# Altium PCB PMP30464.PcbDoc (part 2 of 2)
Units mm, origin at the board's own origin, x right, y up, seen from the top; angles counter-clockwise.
Board outline 89.03 x 50.29 mm, 4 copper layers (Top Layer, GND, Signal Layer, Bottom Layer), stack 2.028 mm thick; 80 components, 45 nets, 213 pads, 174 vias.
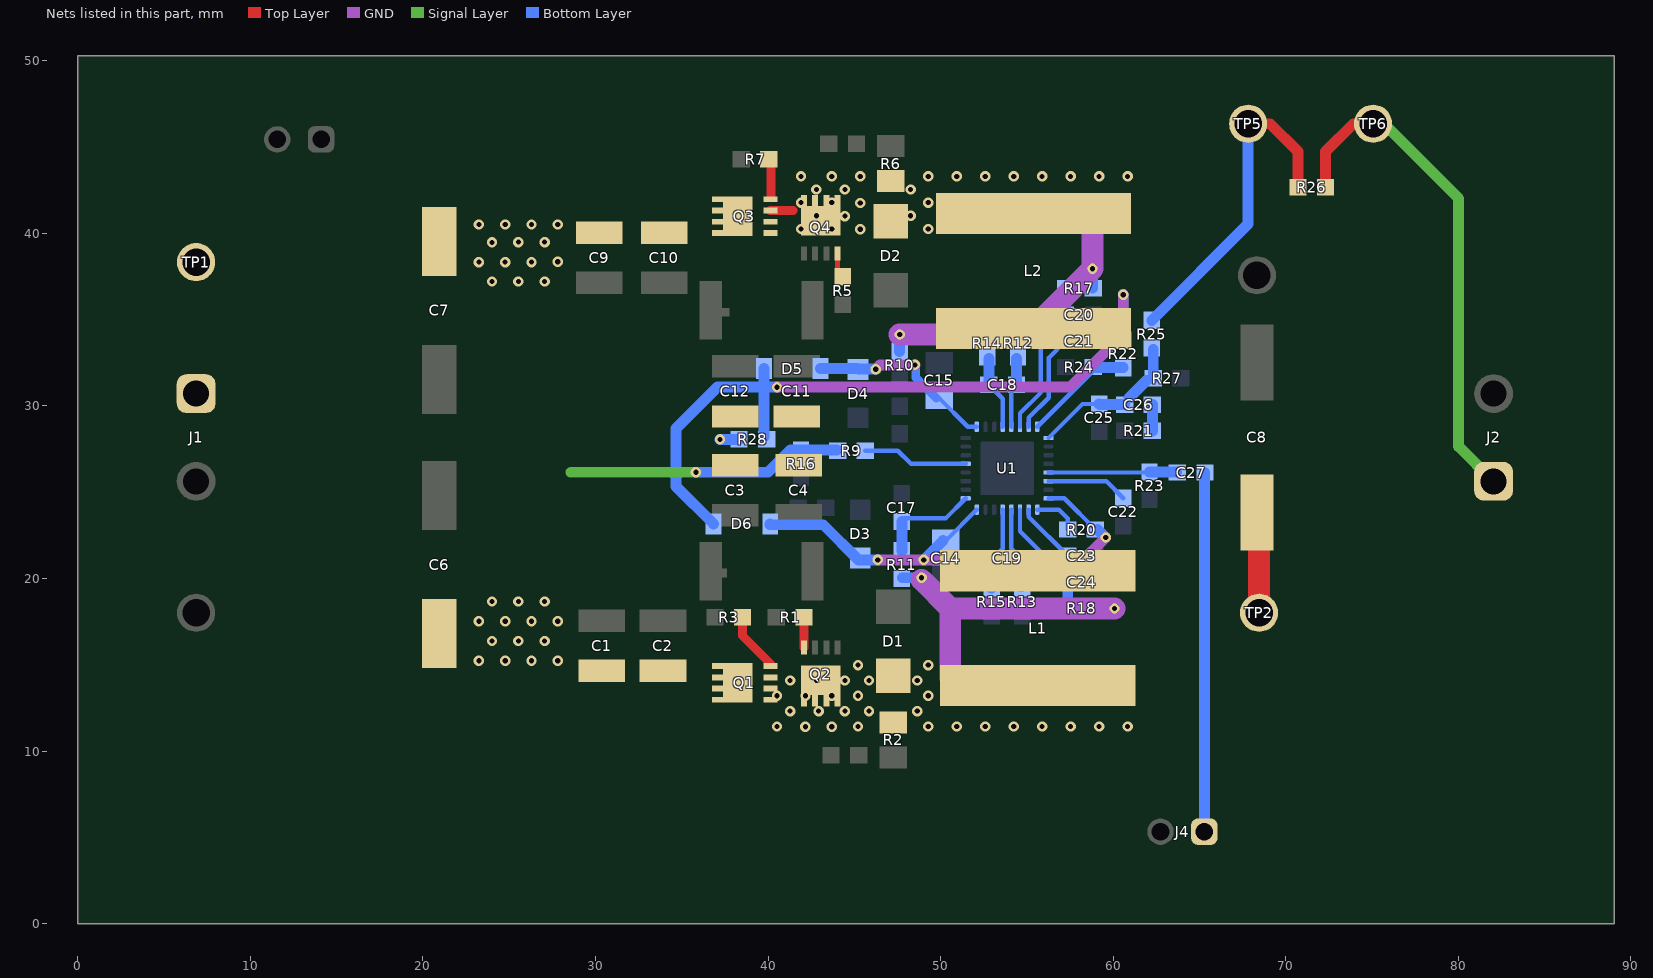
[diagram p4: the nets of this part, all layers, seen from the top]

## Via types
v1: diameter 0.6, hole 0.3, Top Layer to Bottom Layer, 170 vias
v2: diameter 5, hole 3, Top Layer to Bottom Layer, 4 vias

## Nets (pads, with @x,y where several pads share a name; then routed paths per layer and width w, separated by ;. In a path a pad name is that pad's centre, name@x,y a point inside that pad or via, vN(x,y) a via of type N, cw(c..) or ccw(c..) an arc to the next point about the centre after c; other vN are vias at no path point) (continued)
NetC17_2: C17.2 R11.2 U1.25 | length 6
  Bottom Layer w0.254: C17.2@47.75,23.312 47.923,23.485 50.283,23.485 U1.25@51.446,24.648
  Bottom Layer w0.635: R11.2@47.75,21.61 C17.2@47.75,23.312
NetC18_1: C18.1 R12.1 U1.5 | length 3.7
  Bottom Layer w0.254: U1.5@54.096,28.798 C18.1@54.096,30.928
  Bottom Layer w0.635: C18.1@54.392,31.224 R12.1@54.392,32.748
NetC18_2: C18.2 R14.1 U1.4 | length 4.3
  Bottom Layer w0.254: C18.2@52.792,31.224 53.596,30.42 U1.4@53.596,28.798
  Bottom Layer w0.635: C18.2@52.792,31.224 R14.1@52.792,32.748
NetC19_1: C19.1 R13.1 U1.20 | length 4.7
  Bottom Layer w0.254: U1.20@54.096,23.998 54.096,21.741 C19.1@54.646,21.191
  Bottom Layer w0.635: R13.1@54.646,19.54 C19.1@54.646,21.191
NetC19_2: C19.2 R15.1 U1.21 | length 4.8
  Bottom Layer w0.254: C19.2@53.046,21.191 53.596,21.741 U1.21@53.596,23.998
  Bottom Layer w0.635: R15.1@52.957,19.451 52.957,21.102 C19.2@53.046,21.191
NetC20_1: C20.1 R17.2 U1.6 | length 9.4
  Bottom Layer w0.254: U1.6@54.596,28.798 54.596,29.577 55.807,30.788 55.807,33.303 56.261,33.757 56.261,34.798 56.751,35.288 C20.1@57.237,35.288
  Bottom Layer w0.635: C20.1@57.237,35.288 R17.2@57.237,36.812
NetC21_1: C21.1 U1.7 | length 5.9
  Bottom Layer w0.254: U1.7@55.096,28.798 55.096,29.315 56.261,30.48 56.261,32.788 C21.1@57.237,33.764
NetC22_2: C22.2 U1.14 | length 4.7
  Bottom Layer w0.254: U1.14@56.246,25.648 59.587,25.648 C22.2@60.577,24.658
NetC23_1: C23.1 U1.18 | length 3.6
  Bottom Layer w0.254: U1.18@55.096,23.998 55.096,23.586 C23.1@57.364,21.318
NetC24_1: C24.1 R18.1 U1.19 | length 7.5
  Bottom Layer w0.254: U1.19@54.596,23.998 54.596,22.747 56.007,21.336 56.007,20.066 56.279,19.794 C24.1@57.364,19.794
  Bottom Layer w0.635: R18.1@57.364,18.27 C24.1@57.364,19.794
NetC25_2: C25.2 C26.2 R25.1 R27.2 U1.9 | length 8.3
  Bottom Layer w0.254: U1.9@56.246,28.148 58.217,30.119 C25.2@59.18,30.119
  Bottom Layer w0.635: C25.2@59.18,30.119 59.218,30.081 C26.2@60.666,30.081 ; C26.2@60.92,30.473 R27.2@61.925,31.478 ; R27.2@62.317,31.605 R25.1@62.317,33.276
NetC26_1: C26.1 R21.1 | length 1.5
  Bottom Layer w0.635: R21.1@62.266,28.557 C26.1@62.266,30.081
NetC27_2: C27.2 J4.1 | length 20.8
  Bottom Layer w0.635: J4.1@65.278,5.334 C27.2@65.278,26.144
NetQ1_4: Q1.4 R3.1 | length 3.4
  Top Layer w0.508: R3.1@38.517,17.762 38.517,16.681 Q1.4@40.144,15.054
NetQ2_4: Q2.4 R1.1 | length 1.8
  Top Layer w0.508: Q2.4@42.076,15.998 R1.1@42.076,17.759
NetQ3_4: Q3.4 R7.1 | length 2.2
  Top Layer w0.508: Q3.4@40.168,42.081 R7.1@40.168,44.305
NetQ4_4: Q4.4 R5.1 | length 1.1
  Top Layer w0.305: R5.1@44.026,37.78 Q4.4@44.026,38.83
NetR9_1: R9.1 U1.29 | length 6.1
  Bottom Layer w0.254: R9.1@45.629,27.414 47.516,27.414 48.282,26.648 U1.29@51.446,26.648
NetR20_1: R20.1 U1.17 | length 2.6
  Bottom Layer w0.254: U1.17@55.596,23.998 56.846,23.998 57.364,23.48 R20.1@57.364,22.842
NetR22_1: R22.1 R24.2 U1.8 | length 6.3
  Bottom Layer w0.254: U1.8@55.596,28.798 R24.2@58.839,32.041
  Bottom Layer w0.635: R24.2@58.877,32.22 R22.1@60.579,32.22
NetR25_2: R25.2 R26.1 TP5.1 | length 20
  Top Layer w0.635: TP5.1@67.818,46.355 69.088,46.355 70.701,44.742 R26.1@70.701,42.672
  Bottom Layer w0.635: R25.2@62.23,34.963 67.818,40.551 TP5.1@67.818,46.99
SW1: D2.1 L2.1 Q3.1 Q3.2 Q3.3 Q4.5 Q4.6 Q4.7 Q4.8 Q4.9 R6.2 R10.2 R17.1 | length 18.8
  Top Layer w0.508: Q3.3@40.144,41.328 41.455,41.328
  GND w1.27: v1(47.623,34.145) 54.989,34.145 v1(58.799,37.955) 58.799,40.638
  Bottom Layer w0.635: R10.2@47.623,33.167 v1(47.623,34.145) ; R17.1@58.799,36.85 v1(58.799,37.955)
  other v1: 45.337,40.241 41.91,40.259 43.688,40.259 49.276,40.259 44.448,41.003 42.799,41.021 48.26,41.021 45.337,41.765 41.91,41.783 43.688,41.783 49.276,41.783 42.799,42.545 44.45,42.545 48.26,42.545 41.91,43.307 43.688,43.307 45.339,43.307 49.276,43.307 50.927,43.307 52.578,43.307 54.229,43.307 55.88,43.307 57.531,43.307 59.182,43.307 60.833,43.307
SW2: D1.1 L1.1 Q1.1 Q1.2 Q1.3 Q2.5 Q2.6 Q2.7 Q2.8 Q2.9 R2.2 R11.1 R18.2 | length 18.1
  GND w1.27: v1@48.893,19.93 50.553,18.27 ; 50.553,14.231 50.553,18.27 ; v1(60.069,18.27) 50.553,18.27
  Bottom Layer w0.635: R11.1@47.788,20.048 v1(48.893,20.048) ; R18.2@58.964,18.27 v1(60.069,18.27)
  other v1: 42.162,11.412 43.686,11.412 40.513,11.43 45.212,11.43 49.276,11.43 50.927,11.43 52.578,11.43 54.229,11.43 55.88,11.43 57.531,11.43 59.182,11.43 60.833,11.43 41.275,12.319 42.926,12.319 44.45,12.319 45.847,12.319 48.641,12.319 40.513,13.208 42.164,13.208 43.688,13.208 45.212,13.208 49.276,13.208 41.275,14.097 42.799,14.097 44.45,14.097 45.847,14.097 48.641,14.097 45.212,14.986 49.276,14.986
SYNC: C27.1 R23.2 U1.13 | length 7.4
  Bottom Layer w0.254: U1.13@56.246,26.148 R23.2@62.067,26.148
  Bottom Layer w0.635: R23.2@62.101,26.182 C27.1@63.676,26.182
VCC1: C15.1 D4.2 D5.1 U1.1 | length 10.8
  GND w0.635: v1(46.239,32.131) 46.493,32.385 v1(48.514,32.385)
  Bottom Layer w0.254: C15.1@49.909,30.462 51.573,28.798 U1.1@52.096,28.798
  Bottom Layer w0.508: v1(48.514,32.385) 48.552,32.347 48.552,31.654 C15.1@49.744,30.462
  Bottom Layer w0.635: D5.1@43.039,32.17 D4.2@45.156,32.17 ; D4.2@45.225,32.131 v1(46.239,32.131)
VCC2: C14.2 D3.2 D6.1 R20.2 U1.16 U1.24 | length 29.1
  GND w0.635: v1(46.355,21.082) v1(49.022,21.082) 58.268,21.082 v1(59.563,22.377)
  Bottom Layer w0.254: C14.2@50.305,22.207 U1.24@52.096,23.998 ; U1.16@56.246,24.648 57.158,24.648 R20.2@58.964,22.842
  Bottom Layer w0.635: D6.1@40.118,23.174 40.118,23.119 43.194,23.119 45.231,21.082 v1(46.355,21.082) ; v1(49.022,21.082) C14.2@50.147,22.207 ; R20.2@59.098,22.842 v1(59.563,22.377)
VCCDIS: D5.2 D6.2 R22.2 R28.1 | length 43.5
  GND w0.635: v1(40.513,31.091) 57.507,31.091 60.579,34.163 v1(60.579,36.449)
  Bottom Layer w0.635: D6.2@36.844,23.174 34.671,25.346 34.671,28.702 37.06,31.091 39.765,31.091 ; R28.1@39.765,28.219 39.765,31.091 ; D5.2@39.765,32.17 39.765,31.091 ; v1(40.513,31.091) 39.765,31.091 ; R22.2@60.579,33.82 v1(60.579,36.449)
VIN: C1.1 C2.1 C6.1 C7.1 C9.1 C10.1 J1.1 Q1.5 Q1.6 Q1.7 Q1.8 Q1.9 Q3.5 Q3.6 Q3.7 Q3.8 Q3.9 R9.2 R16.2 TP1.1 | length 16
  Signal Layer w0.635: 28.575,26.162 v1(35.814,26.162)
  Bottom Layer w0.635: v1(35.814,26.162) 40.005,26.162 41.295,27.452 42.289,27.452 R9.2@43.991,27.452
  other v1: 23.241,15.24 24.765,15.24 26.289,15.24 27.813,15.24 24.003,16.383 25.527,16.383 27.051,16.383 23.241,17.526 24.765,17.526 26.289,17.526 27.813,17.526 24.003,18.669 25.527,18.669 27.051,18.669 24.003,37.211 25.527,37.211 27.051,37.211 23.239,38.336 24.763,38.336 26.287,38.336 27.813,38.354 24.001,39.479 25.527,39.497 27.051,39.497 23.241,40.513 24.765,40.513 26.289,40.513 27.813,40.513
VOUT: C3.1 C4.1 C8.1 C11.1 C12.1 J2.1 L1.2 L2.2 R26.2 R28.2 TP2.1 TP6.1 | length 36.5
  Top Layer w0.635: R26.2@72.301,42.672 72.301,44.742 73.914,46.355 TP6.1@75.057,46.355
  Top Layer w1.27: TP2.1@68.451,18.016 C8.1@68.451,23.699
  Signal Layer w0.635: TP6.1@75.057,46.99 80.01,42.037 80.01,27.666 J2.1@82.04,25.636
  Bottom Layer w0.635: v1(37.211,28.067) R28.2@38.316,28.067
pads on no net: U1.11
copper on no net:
  other v2: 3.81,3.81 85.22,3.81 3.81,46.35 85.22,46.35

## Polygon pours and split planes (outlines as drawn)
GND on Bottom Layer "GND_L04_P104" (solid, remove dead copper, pour order 104): 5.08,46.99 cw(c6.35,46.99) 6.35,48.26 82.55,48.26 cw(c82.55,46.99) 83.82,46.99 83.82,3.81 cw(c82.55,3.81) 82.55,2.54 6.35,2.54 cw(c6.35,3.81) 5.08,3.81
SW2 on Bottom Layer "SW2_L04_P098" (solid, remove dead copper, pour order 98): 39.751,14.478 cw(c40.64,14.478) 40.64,15.367 60.579,15.367 cw(c60.579,14.478) 61.468,14.478 61.468,11.684 cw(c60.77,11.747) 60.706,11.049 40.64,11.049 cw(c40.513,11.811) 39.751,11.684
SW1 on Bottom Layer "SW1_L04_P092" (solid, remove dead copper, pour order 92): 39.751,40.005 ccw(c40.132,40.005) 40.132,39.624 60.862,39.624 ccw(c60.862,40.132) 61.37,40.132 61.37,43.024 ccw(c60.706,43.024) 60.706,43.688 42.013,43.688 ccw(c42.013,42.926) 41.251,42.926 41.251,41.91 cw(c40.87,41.91) 40.87,41.529 40.005,41.529 ccw(c40.005,41.275) 39.751,41.275
no net on Bottom Layer "NONET_L04_P072" (solid, pour order 72): 2.54,7.62 2.54,8.89 3.81,8.89 3.81,7.62
GND on Top Layer "GND_L01_P114" (solid, remove dead copper, pour order 114): 5.08,46.99 cw(c6.35,46.99) 6.35,48.26 82.55,48.26 cw(c82.55,46.99) 83.82,46.99 83.82,3.81 cw(c82.55,3.81) 82.55,2.54 6.35,2.54 cw(c6.35,3.81) 5.08,3.81
VOUT on Top Layer "VOUT_L01_P112" (solid, remove dead copper, pour order 112): 36.473,29.616 cw(c37.211,29.615) 37.211,30.353 43.307,30.353 ccw(c43.307,30.988) 43.942,30.988 43.942,35.052 cw(c45.212,35.052) 45.212,36.322 62.865,36.322 cw(c62.865,35.433) 63.754,35.433 63.754,29.337 ccw(c64.96,29.527) 65.151,28.321 82.804,28.321 cw(c82.804,27.305) 83.82,27.305 83.82,19.939 cw(c82.677,19.939) 82.677,18.796 45.085,18.796 cw(c45.085,19.939) 43.942,19.939 43.942,24.511 ccw(c43.18,24.511) 43.18,25.273 37.211,25.273 cw(c37.16,25.959) 36.473,25.908
CS2 on Top Layer "CS2_L01_P110" (solid, pour order 110): 41.021,21.971 cw(c41.402,21.971) 41.402,22.352 47.879,22.352 cw(c47.879,21.971) 48.26,21.971 48.26,16.129 cw(c47.879,16.129) 47.879,15.748 41.402,15.748 cw(c41.402,16.129) 41.021,16.129
SW2 on Top Layer "SW2_L01_P096" (solid, remove dead copper, pour order 96): 39.751,14.478 cw(c40.64,14.478) 40.64,15.367 60.833,15.367 cw(c60.833,14.732) 61.468,14.732 61.468,11.557 cw(c60.96,11.557) 60.96,11.049 40.386,11.049 cw(c40.449,11.747) 39.751,11.811
CS1 on Top Layer "CS1_L01_P094" (solid, pour order 94): 40.513,38.989 cw(c40.894,38.989) 40.894,39.37 47.879,39.37 cw(c47.879,38.989) 48.26,38.989 48.26,33.623 cw(c47.879,33.623) 47.879,33.242 40.894,33.242 cw(c40.894,33.623) 40.513,33.623
SW1 on Top Layer "SW1_L01_P086" (solid, remove dead copper, pour order 86): 39.751,40.005 ccw(c40.132,40.005) 40.132,39.624 60.862,39.624 ccw(c60.862,40.132) 61.37,40.132 61.37,43.024 ccw(c60.706,43.024) 60.706,43.688 42.013,43.688 ccw(c42.013,42.926) 41.251,42.926 41.251,41.91 cw(c40.87,41.91) 40.87,41.529 40.005,41.529 ccw(c40.005,41.275) 39.751,41.275
VIN on Top Layer "VIN_L01_P084" (solid, remove dead copper, pour order 84): 18.923,18.796 cw(c19.939,18.796) 19.939,19.812 27.178,19.812 cw(c27.178,18.669) 28.321,18.669 28.321,16.047 ccw(c29.001,16.047) 29.001,15.367 38.608,15.367 cw(c38.608,14.605) 39.37,14.605 39.37,11.43 cw(c38.1,11.43) 38.1,10.16 20.193,10.16 cw(c20.193,11.43) 18.923,11.43
VIN on Top Layer "VIN_L01_P082" (solid, remove dead copper, pour order 82): 20.193,43.307 38.354,43.307 cw(c38.354,42.291) 39.37,42.291 39.37,39.497 cw(c38.1,39.497) 38.1,38.227 28.624,38.227 ccw(c28.663,37.758) 28.194,37.719 28.194,36.449 cw(c27.559,36.449) 27.559,35.814 20.193,35.814 cw(c20.193,37.084) 18.923,37.084 18.923,42.037 cw(c20.193,42.037)
no net on Top Layer "NONET_L01_P078" (solid, pour order 78): 2.54,11.43 2.54,12.7 3.81,12.7 3.81,11.43
GND on Signal Layer "GND_L03_P108" (solid, remove dead copper, pour order 108): 5.08,46.99 cw(c6.35,46.99) 6.35,48.26 82.55,48.26 cw(c82.55,46.99) 83.82,46.99 83.82,3.81 cw(c82.55,3.81) 82.55,2.54 6.35,2.54 cw(c6.35,3.81) 5.08,3.81
SW2 on Signal Layer "SW2_L03_P100" (solid, remove dead copper, pour order 100): 39.751,14.478 cw(c40.64,14.478) 40.64,15.367 60.579,15.367 cw(c60.579,14.478) 61.468,14.478 61.468,11.684 cw(c60.77,11.747) 60.706,11.049 40.64,11.049 cw(c40.513,11.811) 39.751,11.684
SW1 on Signal Layer "SW1_L03_P090" (solid, remove dead copper, pour order 90): 39.751,40.005 ccw(c40.132,40.005) 40.132,39.624 60.862,39.624 ccw(c60.862,40.132) 61.37,40.132 61.37,43.024 ccw(c60.706,43.024) 60.706,43.688 42.013,43.688 ccw(c42.013,42.926) 41.251,42.926 41.251,41.91 cw(c40.87,41.91) 40.87,41.529 40.005,41.529 ccw(c40.005,41.275) 39.751,41.275
no net on Signal Layer "NONET_L03_P074" (solid, pour order 74): 2.54,10.16 3.81,10.16 3.81,8.89 2.54,8.89
VIN on Signal Layer "VIN_L03_P080" (solid, remove dead copper, pour order 80): 5.08,40.513 cw(c6.35,40.513) 6.35,41.783 27.813,41.783 cw(c27.813,40.513) 29.083,40.513 29.083,15.113 cw(c27.813,15.113) 27.813,13.843 6.35,13.843 cw(c6.35,15.113) 5.08,15.113
GND on GND "GND_L02_P106" (solid, remove dead copper, pour order 106): 5.08,46.99 cw(c6.35,46.99) 6.35,48.26 82.55,48.26 cw(c82.55,46.99) 83.82,46.99 83.82,3.81 cw(c82.55,3.81) 82.55,2.54 6.35,2.54 cw(c6.35,3.81) 5.08,3.81
SW2 on GND "SW2_L02_P102" (solid, remove dead copper, pour order 102): 39.751,14.478 cw(c40.64,14.478) 40.64,15.367 60.579,15.367 cw(c60.579,14.478) 61.468,14.478 61.468,11.684 cw(c60.77,11.747) 60.706,11.049 40.64,11.049 cw(c40.513,11.811) 39.751,11.684
SW1 on GND "SW1_L02_P088" (solid, remove dead copper, pour order 88): 39.751,40.005 ccw(c40.132,40.005) 40.132,39.624 60.862,39.624 ccw(c60.862,40.132) 61.37,40.132 61.37,43.024 ccw(c60.706,43.024) 60.706,43.688 42.013,43.688 ccw(c42.013,42.926) 41.251,42.926 41.251,41.91 cw(c40.87,41.91) 40.87,41.529 40.005,41.529 ccw(c40.005,41.275) 39.751,41.275
no net on GND "NONET_L02_P076" (solid, pour order 76): 2.54,10.16 2.54,11.43 3.81,11.43 3.81,10.16
no net on Top Overlay "NONET_L-01_P-001" (solid): 17.526,2.984 17.526,5.112 19.653,5.112 19.653,2.984

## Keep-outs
Keep-Out Layer:
  text ".Layer_Name" at 14.656,-21.806 h1.52

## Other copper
Top Layer:
  pour cut-out: 49.624,15.367 49.624,18.796 61.624,18.796 61.624,15.367
  pour cut-out: 48.641,36.322 49.403,36.322 49.403,39.624 61.37,39.624 61.37,36.322
  text ".Layer_Name" at 14.656,-21.806 h1.52
Bottom Layer:
  text ".Layer_Name" at 14.656,-21.806 h1.52

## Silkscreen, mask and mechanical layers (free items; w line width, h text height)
Top Overlay:
  lines w0.3: 4.953,6.35 4.953,43.561 ; 6.35,48.387 82.55,48.387 ; 6.477,2.54 82.677,2.54 ; 83.82,6.477 83.82,43.688
  text "EN" at 14.732,41.148 h1.85 r90
  text "GND" at 12.065,39.751 h1.85 r90
  text "IN+" at 5.842,34.544 h1.85
  text "OUT-" at 79.121,33.528 h1.85
  text "IN-" at 6.223,21.59 h1.85
  text "OUT+" at 79.121,21.082 h1.85
  text "SYNC" at 65.913,7.112 h1.85 r90
  text "GND" at 63.246,6.985 h1.85 r90
  text "PMP30464 Rev" at 7.493,3.683 h0.8
  text ".Layer_Name" at 14.656,-21.806 h1.52
Bottom Overlay:
  lines w0.3: 4.953,6.35 4.953,43.561 ; 6.35,48.387 82.55,48.387 ; 6.477,2.54 82.677,2.54 ; 83.82,6.477 83.82,43.688
  text ".Layer_Name" at 14.656,-21.806 h1.52
Top Paste:
  text ".Layer_Name" at 14.656,-21.806 h1.52
Bottom Paste:
  text ".Layer_Name" at 14.656,-21.806 h1.52
Top Solder:
  text ".Layer_Name" at 14.656,-21.806 h1.52
  text ".Layer_Name" at 14.656,-21.806 h1.52
Bottom Solder:
  text ".Layer_Name" at 14.656,-21.806 h1.52
Drill Guide:
  text ".Layer_Name" at 14.656,-21.806 h1.52
M1 Board Outline:
  lines w0.3: 132.207,0 132.334,0.127
  lines w0.5: 0,0 89.027,0 89.027,50.292 0,50.292 0,0
  text ".Layer_Name" at 14.656,-21.806 h1.52
M2 Board Dimensions:
  rectangle: 3.175,-10.16 12.7,-6.985
  rectangle: 0,-6.985 3.175,-3.81
  lines w0.178: 0,-6.985 25.4,-6.985 ; 3.175,-10.16 3.175,-3.81 ; 6.35,-10.16 6.35,-3.81 ; 12.7,-10.16 12.7,-3.81 ; 19.05,-10.16 19.05,-3.81 ; 0,-10.16 0,-3.81 25.4,-3.81 25.4,-10.16 0,-10.16
  text ".Layer_Name" at 14.656,-21.806 h1.52
M3 3D STEP Top:
  text ".Layer_Name" at 14.656,-21.806 h1.52
M4 3D STEP Bottom:
  text ".Layer_Name" at 14.656,-21.806 h1.52
M5 Assembly Top:
  lines w0.254: -7.417,-23.626 160.223,-23.626 ; -7.417,-18.462 160.274,-18.462 ; -7.417,-13.297 -7.417,-28.791 94.31,-28.791 160.274,-28.791 160.274,-13.297 -7.404,-13.297 -7.404,-28.791 32.614,-28.791 ; 55.194,-28.791 55.194,-13.297 ; 87.376,-18.462 87.376,-13.297 ; 108.712,-18.462 108.712,-13.297 ; 124.511,-28.956 124.511,-23.804
  text "COMPONENTS MARKED 'DNP' SHOULD NOT BE POPULATED." at 29.299,-8.09 h1.52
  text "ASSEMBLY VARIANT:" at 29.286,-11.024 h1.52
  text ".VariantName" at 55.601,-11.024 h1.52
  text "PCB VIEWED FROM TOP SIDE" at -5.804,-16.654 h1.52
  text "BOARD #:" at 57.099,-16.654 h1.52
  text ".PRJ_Number" at 70.955,-16.654 h1.52
  text "REV:" at 92.405,-16.654 h1.52
  text ".PCB_Rev" at 99.809,-16.654 h1.52
  text "SVN REV:" at 113.69,-16.654 h1.52
  text ".VersionControl_RevNumber" at 126.543,-16.654 h1.52
  text "TID #:" at 57.099,-21.819 h1.52
  text ".TID" at 70.955,-21.819 h1.52
  text "PLOT NAME =" at -5.804,-27.034 h1.52
  text ".plot_File_Name" at 14.656,-27.034 h1.52
  text "GENERATED    :" at 57.15,-27.034 h1.52
  text ".Print_Date" at 79.235,-27.034 h1.52
  text ".Print_Time" at 97.752,-27.034 h1.52
  text "TEXAS INSTRUMENTS" at 129.87,-27.034 h1.52
M6 Assembly Bottom:
  lines w0.254: -7.429,-18.474 160.261,-18.474 ; -7.379,-23.639 160.261,-23.639 ; 28.334,-28.969 28.334,-23.817 ; 44.133,-18.474 44.133,-13.31 ; 65.468,-18.474 65.468,-13.31 ; 97.65,-28.804 97.65,-13.31 ; 120.231,-28.804 160.249,-28.804 160.249,-13.31 -7.429,-13.31 -7.429,-28.804 58.534,-28.804 160.261,-28.804 160.261,-13.31
  text "COMPONENTS MARKED 'DNP' SHOULD NOT BE POPULATED." at 154.991,-8.077 h1.52
  text ".VariantName" at 128.473,-11.024 h1.52
  text "ASSEMBLY VARIANT:" at 154.864,-11.024 h1.52
  text ".VersionControl_RevNumber" at 26.302,-16.667 h1.52
  text "SVN REV:" at 39.154,-16.667 h1.52
  text ".PCB_Rev" at 53.035,-16.667 h1.52
  text "REV:" at 60.439,-16.667 h1.52
  text ".PRJ_Number" at 81.89,-16.667 h1.52
  text "BOARD #:" at 95.745,-16.667 h1.52
  text "PCB VIEWED FROM BOTTOM SIDE" at 158.648,-16.667 h1.52
  text ".TID" at 81.89,-21.831 h1.52
  text "TID #:" at 95.745,-21.831 h1.52
  text "TEXAS INSTRUMENTS" at 22.974,-27.047 h1.52
  text ".Print_Time" at 55.093,-27.047 h1.52
  text ".Print_Date" at 73.609,-27.047 h1.52
  text "GENERATED    :" at 95.694,-27.047 h1.52
  text ".plot_File_Name" at 138.189,-27.047 h1.52
  text "PLOT NAME =" at 158.648,-27.047 h1.52
M9 Title Sheet:
  drawing of 57 lines, arcs and shapes, not listed
  text "1" at 18.792,204.127 h1.78
  text "2" at 82.182,204.127 h1.78
  text "3" at 145.411,204.127 h1.78
  text "4" at 209.08,204.127 h1.78
  text "5" at 272.555,204.127 h1.78
  text "6" at 336.182,204.127 h1.78
  text "A" at -10.579,175.095 h1.78
  text "A" at 365.341,175.095 h1.78
  text "B" at -10.579,114.643 h1.78
  text "B" at 365.341,114.643 h1.78
  text "C" at -10.579,54.318 h1.78
  text "C" at 365.341,54.318 h1.78
  text "PROJECT TITLE:" at 288.125,7.048 h1.14
  text ".PRJ_Title" at 289.395,3.662 h1.78
  text "DESIGNED FOR:" at 288.125,-0.597 h1.14
  text ".PRJ_Customer" at 289.395,-4.153 h1.78
  text "D" at -10.579,-5.88 h1.78
  text "D" at 365.341,-5.88 h1.78
  text "FILE NAME:" at 288.125,-8.217 h1.14
  text ".PCB_File_Name_No_Path" at 289.395,-11.265 h1.78
  text "Texas Instruments (TI) and/or its licensors do not warrant the accuracy or completeness of this specification" at 161.9,-15.376 h1.14
  text "ENGINEER:" at 288.125,-15.583 h1.14
  text "LAYOUT BY:" at 326.352,-15.583 h1.14
  text "or any information contained therein. TI and/or its licensors do not warrant that this design will meet" at 160.757,-18.237 h1.14
  text ".PRJ_Engineer" at 289.395,-19.52 h1.78
  text ".PCB_Layout" at 327.635,-19.52 h1.78
  text "the specifications, will be suitable for your application or fit for any particular purpose, or will operate in" at 160.757,-21.099 h1.14
  text ".Layer_Name" at 14.656,-21.806 h1.52
  text "ALTIUM DESIGNER VERSION:" at 326.352,-23.457 h1.14
  text "an implementation. TI and/or its licensors do not warrant that the design is production worthy. You should" at 160.757,-23.961 h1.14
  text "completely validate and test your design implementation to confirm the system functionality for your application." at 161.9,-26.822 h1.14
  text ".print_Scale" at 289.395,-26.843 h1.78
  text ".Application_BuildNumber" at 327.635,-26.843 h1.78
  text "1" at 18.792,-32.093 h1.78
  text "2" at 82.182,-32.093 h1.78
  text "3" at 145.411,-32.093 h1.78
  text "4" at 209.08,-32.093 h1.78
  text "5" at 272.555,-32.093 h1.78
  text "6" at 336.182,-32.093 h1.78
M10 Fab Notes:
  drawing of 173 lines, arcs and shapes, not listed
  text "DESIGN INFORMATION" at 314.376,157.505 h1.52
  text "MIN. TRACK WIDTH:" at 298.004,152.933 h1.52
  text "8" at 325.849,152.933 h1.52
  text "MIL" at 329.78,152.933 h1.52
  text "MIN. CLEARANCE:" at 298.004,149.581 h1.52
  text "0.2" at 324.325,149.581 h1.52
  text "mm" at 329.78,149.581 h1.52
  text "MIN. VIA PAD SIZE:" at 298.004,146.228 h1.52
  text "24" at 325.087,146.228 h1.52
  text "MIL" at 329.78,146.228 h1.52
  text "0.05mm (2MIL)" at 315.657,142.628 h1.52
  text "MINIMUM ANNULAR RING" at 289.642,142.52 h1.52
  text "EXTERNAL" at 333.641,142.52 h1.52
  text "PER" at 294.722,139.522 h1.52
  text "IPC-D-275 CLASS 2 LEVEL C" at 300.31,139.522 h1.52
  text "MIL, HOLES" at 338.111,136.67 h1.52
  text "+/-" at 328.143,136.652 h1.52
  text "+/-" at 349.834,136.652 h1.52
  text "REGISTRATION TOLERANCES:" at 289.642,136.525 h1.52
  text "METAL" at 320.116,136.525 h1.52
  text "5" at 334.752,136.525 h1.52
  text "3" at 355.91,136.525 h1.52
  text "MIL" at 358.863,136.525 h1.52
  text "+/-" at 349.834,133.655 h1.52
  text "HOLE SIZE TOLERANCE (UNLESS OTHERWISE SPECIFIED):" at 289.642,133.528 h1.52
  text "3" at 355.91,133.528 h1.52
  text "MIL" at 358.863,133.528 h1.52
  text "MATERIAL:" at 287.743,128.208 h1.52
  text "FR-4 High Tg" at 312.799,124.643 h1.52
  text "FR-408" at 298.436,124.425 h1.52
  text "OTHER" at 336.231,124.425 h1.52
  text "X" at 308.864,124.333 h1.52
  text "62 MIL (1.6mm) +/-10%" at 306.567,120.292 h1.52
  text "THICKNESS:" at 289.642,120.184 h1.52
  text "X" at 303.311,120.184 h1.52
  text "OTHER" at 339.203,120.184 h1.52
  text "TOLERANCE:" at 289.642,116.17 h1.52
  text "X" at 310.96,116.17 h1.52
  text "ANSI IPC-6012 TYPE 3 CLASS 2" at 315.709,116.17 h1.52
  text "OTHER +/-" at 315.708,112.208 h1.52
  text "BOW & TWIST:" at 289.642,108.22 h1.52
  text "X" at 310.96,108.22 h1.52
  text "ANSI IPC-6012 TYPE 3 CLASS 2" at 315.709,108.22 h1.52
  text "OTHER +/-" at 315.708,104.194 h1.52
  text "DRILLING:" at 287.743,100.676 h1.52
  text "REFERENCE:" at 289.642,97.705 h1.52
  text "X" at 306.107,97.705 h1.52
  text "AS SHOWN" at 310.857,97.705 h1.52
  text "X" at 328.992,97.705 h1.52
  text "NC_DRILL FILES" at 332.472,97.705 h1.52
  text "PTH COPPER THICKNESS:" at 289.642,93.691 h1.52
  text "X" at 318.35,93.691 h1.52
  text "20-30 um" at 321.83,93.691 h1.52
  text "OTHER" at 340.041,93.691 h1.52
  text "BOARD FINISH:" at 287.743,89.653 h1.52
  text "SILKSCREEN:" at 291.685,86.656 h1.52
  text "X" at 315.784,86.656 h1.52
  text "TOP" at 318.985,86.656 h1.52
  text "X" at 328.738,86.656 h1.52
  text "BOTTOM" at 331.964,86.656 h1.52
  text "SILKSCREEN COLOR:" at 291.685,82.414 h1.52
  text "X" at 315.758,82.414 h1.52
  text "WHITE" at 318.985,82.414 h1.52
  text "OTHER" at 331.964,82.414 h1.52
  text "X" at 319.086,78.37 h1.52
  text "GREEN" at 322.312,78.37 h1.52
  text "OTHER" at 338.009,78.37 h1.52
  text "SOLDER RESIST COLOR:" at 291.685,78.096 h1.52
  text "X" at 319.086,74.052 h1.52
  text "MATTE" at 322.312,74.052 h1.52
  text "SEMI-GLOSS" at 337.998,74.036 h1.52
  text "IMMERSION GOLD (ENIG)" at 314.692,69.264 h1.52
  text "ENEPIG" at 348.666,69.18 h1.52
  text "SURFACE FINISH:" at 287.743,69.155 h1.52
  text "X" at 309.944,69.155 h1.52
  text "IMM. TIN/SILVER OR EQUIV" at 296.113,65.167 h1.52
  text "OTHER" at 332.472,65.167 h1.52
  text "ARRAY/PANEL:" at 287.743,60.621 h1.52
  text "CUT AND TRIM PER M1 BOARD OUTLINE" at 314.692,60.512 h1.52
  text "N.C. ROUTE" at 314.692,56.658 h1.52
  text "X" at 331.939,56.658 h1.52
  text "V. SCORE" at 336.689,56.658 h1.52
  text "CERTIFICATION:" at 287.743,53.178 h1.52
  text "MATERIALS AND WORKMANSHIP FOR ALL PCBS" at 306.158,53.178 h1.52
  text "TO MEET OR EXCEED THE REQUIREMENTS OF:" at 306.158,50.689 h1.52
  text "X" at 296.671,47.222 h1.52
  text "ANSI IPC-A-600F CLASS ->" at 300.202,47.222 h1.52
  text "X" at 341.834,47.222 h1.52
  text "2" at 344.855,47.222 h1.52
  text "1" at 336.854,47.184 h1.52
  text "3" at 353.846,47.184 h1.52
  text "X" at 317.348,43.171 h1.52
  text "RoHS" at 320.826,43.171 h1.52
  text "OTHER" at 337.194,43.171 h1.52
  text "PER ORDER" at 347.28,43.171 h1.52
  text "ALL BOARDS MUST MEET OR EXCEED UL94-V0 REQUIREMENTS." at 288.442,38.964 h1.52
  text "PCB MUST BEAR THE UL94V-0 UL REGISTERED MATERIAL ID NUMBER" at 288.442,35.916 h1.52
  text "ADDITIONAL REQUIREMENTS:" at 287.743,31.512 h1.52
  text "MICROSECTION:" at 289.642,28.591 h1.52
  text "YES" at 312.648,28.591 h1.52
  text "REQUIRED" at 334.53,24.625 h1.52
  text "BARE BOARD ELEC. TEST:" at 289.642,24.553 h1.52
  text "NONE" at 322.808,24.553 h1.52
  text "X" at 331.304,24.553 h1.52
  text "PER ORDER" at 349.566,24.553 h1.52
  text ".Layer_Name" at 14.656,-21.806 h1.52
M11 Gerber Information:
  lines w0.254: -7.417,-23.626 160.223,-23.626 ; -7.417,-18.462 160.274,-18.462 ; -7.417,-13.297 -7.417,-28.791 94.31,-28.791 160.274,-28.791 160.274,-13.297 -7.404,-13.297 -7.404,-28.791 32.614,-28.791 ; 55.194,-28.791 55.194,-13.297 ; 87.376,-18.462 87.376,-13.297 ; 108.712,-18.462 108.712,-13.297 ; 124.511,-28.956 124.511,-23.804
  text "ALL ARTWORK VIEWED FROM TOP SIDE" at -5.804,-16.654 h1.52
  text "BOARD #:" at 57.099,-16.654 h1.52
  text ".PRJ_Number" at 70.955,-16.654 h1.52
  text "REV:" at 92.405,-16.654 h1.52
  text ".PCB_Rev" at 99.809,-16.654 h1.52
  text "SVN REV:" at 113.69,-16.654 h1.52
  text ".VersionControl_RevNumber" at 126.543,-16.654 h1.52
  text "LAYER NAME =" at -5.804,-21.806 h1.52
  text "TID #:" at 57.099,-21.819 h1.52
  text ".TID" at 70.955,-21.819 h1.52
  text "PLOT NAME =" at -5.804,-27.034 h1.52
  text ".plot_File_Name" at 14.656,-27.034 h1.52
  text "GENERATED    :" at 57.15,-27.034 h1.52
  text ".Print_Date" at 79.235,-27.034 h1.52
  text ".Print_Time" at 97.752,-27.034 h1.52
  text "TEXAS INSTRUMENTS" at 129.87,-27.034 h1.52
M12 Stackup:
  drawing of 295 lines, arcs and shapes, not listed
  text "Layer" at 248.871,198.882 h1.52
  text "Name" at 259.283,198.882 h1.52
  text "Material" at 282.898,198.882 h1.52
  text "Thickness" at 304.736,198.882 h1.52
  text "Constant" at 321.242,198.882 h1.52
  text "Board Layer Stack" at 335.717,198.882 h1.52
  text "1" at 248.871,195.834 h1.52
  text "Top Overlay" at 259.283,195.834 h1.52
  text "2" at 248.871,192.786 h1.52
  text "Top Solder" at 259.283,192.786 h1.52
  text "Solder Resist" at 282.898,192.786 h1.52
  text "0.40mil" at 304.736,192.786 h1.52
  text "3.5" at 321.242,192.786 h1.52
  text "3" at 248.871,189.738 h1.52
  text "Top Layer" at 259.283,189.738 h1.52
  text "Copper" at 282.898,189.738 h1.52
  text "1.40mil" at 304.736,189.738 h1.52
  text "4" at 248.871,186.69 h1.52
  text "Dielectric1" at 259.283,186.69 h1.52
  text "FR-4" at 282.898,186.69 h1.52
  text "59.20mil" at 304.736,186.69 h1.52
  text "4.8" at 321.242,186.69 h1.52
  text "5" at 248.871,183.642 h1.52
  text "GND" at 259.283,183.642 h1.52
  text "Copper" at 282.898,183.642 h1.52
  text "1.42mil" at 304.736,183.642 h1.52
  text "6" at 248.871,180.594 h1.52
  text "Dielectric 3" at 259.283,180.594 h1.52
  text "5.00mil" at 304.736,180.594 h1.52
  text "4.2" at 321.242,180.594 h1.52
  text "7" at 248.871,177.546 h1.52
  text "Signal Layer" at 259.283,177.546 h1.52
  text "Copper" at 282.898,177.546 h1.52
  text "1.42mil" at 304.736,177.546 h1.52
  text "8" at 248.871,174.498 h1.52
  text "Dielectric 2" at 259.283,174.498 h1.52
  text "10.00mil" at 304.736,174.498 h1.52
  text "4.2" at 321.242,174.498 h1.52
  text "9" at 248.871,171.45 h1.52
  text "Bottom Layer" at 259.283,171.45 h1.52
  text "Copper" at 282.898,171.45 h1.52
  text "1.40mil" at 304.736,171.45 h1.52
  text "10" at 248.871,168.402 h1.52
  text "Bottom Solder" at 259.283,168.402 h1.52
  text "Solder Resist" at 282.898,168.402 h1.52
  text "0.40mil" at 304.736,168.402 h1.52
  text "3.5" at 321.242,168.402 h1.52
  text "11" at 248.871,165.354 h1.52
  text "Bottom Overlay" at 259.283,165.354 h1.52
  text ".Layer_Name" at 14.656,-21.806 h1.52
M13 Component Bodies Top:
  text ".Layer_Name" at 14.656,-21.806 h1.52
M14 Component Bodies Bottom:
  text ".Layer_Name" at 14.656,-21.806 h1.52
M15 Courtyards Top:
  text ".Layer_Name" at 14.656,-21.806 h1.52
M16 Courtyards Bottom:
  text ".Layer_Name" at 14.656,-21.806 h1.52
Drill Drawing:
  text ".Layer_Name" at 14.656,-21.806 h1.52

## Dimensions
0,0 to 89.027,0 on M2 Board Dimensions
0,-10.16 to 25.4,-10.16 on M2 Board Dimensions
0,0 to -3.302,50.165 on M2 Board Dimensions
